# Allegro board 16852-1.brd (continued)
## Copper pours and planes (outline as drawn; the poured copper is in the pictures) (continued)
+DC_IN on L4: 51.56,119.87 49.28,119.87 49.02,119.62 49.02,111.36 53.82,106.56 60.76,106.56 61.98,107.78 61.98,110.09 61.21,110.86 56.77,110.86 52.58,115.05 52.58,118.86
+DC_IN on L6: 51.36,119.85 48.97,119.85 48.72,119.59 48.72,113.47 54.15,108.04 61.06,108.04 61.34,108.32 62.99,108.32 63.12,108.44 63.12,111.21 62.92,111.41 56.08,111.41 52.55,114.95 52.55,119.62 52.3,119.87 51.38,119.87
+DC_IN_C on TOP: 53.85,109.84 53.72,109.97 53.72,118.1 53.98,118.35 56.92,118.35 57.15,118.12 57.15,116.57 55.5,114.92 55.5,110.22 55.12,109.84 ; 3 cut-outs
+DC_IN_C on BOTTOM: 51.05,114.16 50.67,114.54 50.67,117.79 52.65,119.77 55.83,119.77 57.15,118.45 57.15,116.57 54.74,114.16
+SDC_IN on TOP: 66.42,104.13 66.29,104.25 66.29,106.92 66.93,107.55 69.34,107.55 69.47,107.43 69.47,106.28 69.6,106.16 70.56,106.16 70.84,105.88 70.84,105.62 71.17,105.29 71.81,105.29 71.86,105.24 72.67,105.24 72.77,105.14 72.77,104.25 72.64,104.13 ; 2 cut-outs
AD+ on TOP: 63.63,107.3 63.37,107.55 63.37,110.6 64.77,112 64.77,112.51 64.9,112.63 72.9,112.63 73.91,111.62 73.91,110.48 73.41,109.97 70.87,109.97 70.61,109.71 70.61,108.32 70.23,107.94 66.8,107.94 66.17,107.3 ; 5 cut-outs
AUD_AGND on TOP: 18.29,3.62 17.7,4.2 17.7,4.94 17.86,5.09 18.85,5.09 19.28,5.52 20.85,5.52 21.03,5.34 22,5.34 22.12,5.22 22.12,4.84 22.33,4.63 23.22,4.63 23.47,4.38 23.47,3.77 23.32,3.62 ; 5 cut-outs
AUD_AGND on TOP: 30.25,1.97 30.1,2.12 30.1,6.34 29.97,6.46 28.7,6.46 28.45,6.72 28.45,7.22 28.57,7.35 30.73,7.35 31.11,7.73 31.75,7.73 31.88,7.61 31.88,2.04 31.8,1.97 ; 5 cut-outs
AUD_AGND on L2VCC: 21.51,9.57 21.77,9.32 25.07,9.32 25.08,9.3 25.08,8.03 26.48,6.64 26.48,3.46 27.1,2.84 29.42,2.84 30.29,3.72 30.29,6.16 29.92,6.53 28.65,6.53 28.51,6.67 28.51,8.7 27.38,9.83 26.49,9.83 26.35,9.97 26.35,10.83 26.37,10.84 28.37,10.84 30.4,8.81 31.42,8.81 31.94,8.29 31.94,1.42 31.49,1.82 30.9,1.96 26.9,1.96 26.03,1.61 25.64,0.76 4.5,0.76 3.63,1.13 3.26,2 3.26,4.8 2.75,6.05 1.5,6.56 1,6.56 0.83,6.63 0.76,6.8 0.76,7.12 2.06,6.71 3.13,7.54 12.5,7.54 13.7,8.4 13.26,9.81 13.26,14.29 13.7,15.7 12.5,16.56 3.26,16.56 3.26,17.31 3.29,17.34 3.94,17.8 4.18,18.55 4.18,18.97 14.65,18.97 15.68,17.94 15.68,16.67 15.92,16.43 19.61,16.43 19.75,16.29 19.75,15.94 19.23,15.42 18.34,15.42 17.97,15.05 17.97,14.38 18.34,14.02 19.23,14.02 19.49,13.75 19.49,12.86 19.82,12.54 21.41,12.54 21.4,9.84 21.4,9.69
AUD_AGND on L5GND: 21.51,9.57 21.77,9.32 25.07,9.32 25.08,9.3 25.08,8.03 26.48,6.64 26.48,3.46 27.1,2.84 29.42,2.84 30.29,3.72 30.29,6.16 29.92,6.53 28.65,6.53 28.51,6.67 28.51,8.7 27.38,9.83 26.49,9.83 26.35,9.97 26.35,10.83 26.37,10.84 28.37,10.84 30.4,8.81 31.42,8.81 31.94,8.29 31.94,1.42 31.49,1.82 30.9,1.96 26.9,1.96 26.03,1.61 25.64,0.76 4.5,0.76 3.63,1.13 3.26,2 3.26,4.8 2.75,6.05 1.5,6.56 1,6.56 0.83,6.63 0.76,6.8 0.76,7.12 2.06,6.71 3.13,7.54 12.5,7.54 13.7,8.4 13.26,9.81 13.26,14.29 13.7,15.7 12.5,16.56 3.26,16.56 3.26,17.31 3.29,17.34 3.94,17.8 4.18,18.55 4.18,18.97 14.65,18.97 15.68,17.94 15.68,16.67 15.92,16.43 19.61,16.43 19.75,16.29 19.75,15.94 19.23,15.42 18.34,15.42 17.97,15.05 17.97,14.38 18.34,14.02 19.23,14.02 19.49,13.75 19.49,12.84 19.8,12.54 21.41,12.54 21.4,9.84 21.4,9.69
AUD_AGND on L7GND: 4.5,0.76 3.63,1.13 3.26,2 3.26,4.8 2.75,6.05 1.5,6.56 1,6.56 0.83,6.63 0.76,6.8 0.76,7.12 2.06,6.71 3.13,7.54 12.5,7.54 13.7,8.4 13.26,9.81 13.26,14.29 13.7,15.7 12.5,16.56 3.26,16.56 3.26,17.31 3.29,17.34 3.94,17.8 4.18,18.55 4.18,18.97 14.81,18.97 15.32,19.48 16.18,19.48 16.45,19.21 16.45,17.94 16.94,17.45 18.84,17.45 18.99,17.31 18.99,16.19 18.72,15.92 18.34,15.92 17.84,15.43 17.84,14.51 19.86,12.49 20.75,12.49 20.89,12.35 20.89,10.73 20.62,10.46 18.21,10.46 17.72,9.97 17.72,8.54 18.21,8.05 19.25,8.05 19.27,8.04 19.33,8.05 19.38,8.05 19.4,8.07 19.43,8.07 19.46,8.12 19.49,8.16 19.49,8.19 19.79,8.68 20.48,8.68 21.02,7.93 21.02,5.75 21.51,5.26 22.81,5.26 23.18,5.62 23.18,6.89 23.32,7.03 26.08,7.03 26.48,6.64 26.48,1.89 25.89,1.45 25.64,0.76
AUD_SPK_L+ on TOP: 33.73,9.87 33.6,9.99 33.6,10.22 33.35,10.48 29.84,10.48 28.8,11.52 26.49,11.52 26.47,11.54 26.47,11.69 26.49,11.72 29.34,11.72 29.49,11.57 34.39,11.57 34.47,11.49 34.47,9.99 34.34,9.87 ; 2 cut-outs
AUD_SPK_L+_C on TOP: 35,9.89 34.92,9.97 34.92,11.19 34.98,11.24 37.41,11.24 37.47,11.19 37.47,9.97 37.39,9.89
AUD_SPK_L+_C on BOTTOM: 34.24,9.51 33.68,10.07 31.11,10.07 31.06,10.12 31.06,11.64 31.14,11.72 34.24,11.72 34.67,11.29 36.37,11.29 36.63,11.03 36.63,9.69 36.45,9.51
AUD_SPK_L- on TOP: 29.62,11.67 29.36,11.92 26.47,11.92 26.44,11.95 26.44,12.1 26.47,12.13 29.01,12.13 29.21,12.33 30.28,12.33 30.68,12.74 34.39,12.74 34.49,12.63 34.49,11.77 34.39,11.67 ; 2 cut-outs
AUD_SPK_L-_C on TOP: 34.95,11.64 34.82,11.77 34.82,12.66 34.95,12.79 37.24,12.79 37.49,12.53 37.49,11.77 37.36,11.64
AUD_SPK_L-_C on BOTTOM: 34.11,7.45 33.43,8.14 30.89,8.14 30.07,8.95 30.07,11.67 30.18,11.77 30.89,11.77 30.89,10.04 31.09,9.84 33.6,9.84 34.54,8.9 36.09,8.9 36.88,9.69 36.88,11.24 36.68,11.44 36.04,11.44 35.97,11.52 35.97,12.41 36.14,12.58 38.15,12.58 38.79,11.95 38.79,8.09 38.15,7.45
AUD_SPK_R+ on TOP: 26.49,12.71 26.44,12.76 26.44,12.89 26.49,12.94 27.84,12.94 28.45,13.55 28.45,13.85 31.14,16.55 31.85,16.55 32.13,16.27 32.77,16.27 32.89,16.14 32.89,15.02 32.84,14.97 31.01,14.97 29.11,13.07 28.78,13.07 28.42,12.71 ; 2 cut-outs
AUD_SPK_R+_C on BOTTOM: 29.03,10.02 29.03,12.3 30.66,13.93 35.03,13.93 35.28,14.18 35.28,15.45 35.38,15.56 36.86,15.56 36.96,15.45 36.96,15.33 36.98,15.3 36.98,13.65 35.28,11.95 30.76,11.95 30.73,11.97 30.18,11.97 29.92,11.72 29.92,10.12 29.82,10.02
AUD_SPK_R- on TOP: 26.48,12.32 26.47,12.33 26.47,12.51 26.49,12.53 28.42,12.53 28.83,12.94 29.18,12.94 31.09,14.84 32.82,14.84 32.85,14.81 32.85,14.48 32.87,14.46 32.87,13.8 32.74,13.68 31.34,13.68 30.12,12.45 29.09,12.45 28.96,12.32 ; 2 cut-outs
AUD_SPK_R-_C on TOP: 33.48,13.4 33.35,13.52 33.35,14.54 33.78,14.97 34.82,14.97 35.71,14.08 35.71,13.57 35.53,13.4
AUD_SPK_R-_C on BOTTOM: 27.08,10.07 27,10.15 27,12.41 30.18,15.58 35.03,15.58 35.13,15.48 35.13,14.26 35,14.13 30.45,14.13 28.8,12.48 28.8,10.15 28.73,10.07
BT+ on TOP: 229.36,23.99 229.24,24.12 229.24,25.13 228.47,25.89 228.47,28.81 228.22,29.07 227.71,29.07 226.69,30.08 226.69,30.77 227.58,31.66 227.58,32.52 227.53,32.57 226.69,32.57 226.69,36.69 226.82,36.82 228.22,36.82 229.74,35.29 229.74,33.26 230.63,32.37 231.01,32.37 231.14,32.24 231.14,31.61 231.39,31.35 231.39,28.56 230.38,27.54 230.38,24.12 230.25,23.99 ; 3 cut-outs
BT+ on TOP: 236.09,22.06 235.97,22.18 235.97,23.1 236.09,23.23 236.85,23.23 236.98,23.1 236.98,22.29 236.75,22.06
BT+ on BOTTOM: 225.55,26.02 225.43,26.15 225.43,28.18 226.31,29.07 226.31,33.77 227.48,34.94 231.27,34.94 231.27,28.68 230.5,27.92 230.5,26.15 230.38,26.02
CHARGER_SRC on TOP: 220.18,18.12 220.01,18.29 220.01,24.37 219.99,24.39 219.99,26.81 220.12,26.93 223.27,26.93 223.52,26.68 223.52,24.32 222.81,23.6 222.81,23.6 222.81,19.93 223.06,19.69 224.37,19.69 224.54,19.52 224.54,18.15 224.51,18.12
CHARGER_SRC on BOTTOM: 220.6,20.81 220.09,21.32 220.09,25.13 220.34,25.39 222.25,25.39 222.63,25 222.63,23.61 222.25,23.23 222.25,21.45 221.62,20.81 ; 5 cut-outs
CHG_AGND on TOP: 241.02,12.08 240.92,12.18 240.92,12.56 241.05,12.69 241.94,12.69 242.06,12.81 242.06,15.48 242.19,15.61 243.28,15.61 243.43,15.45 243.43,14.26 242.95,13.78 242.95,12.3 242.72,12.08 ; 5 cut-outs
CHG_AGND on L6: 229.29,22.59 233.25,22.59 234.37,23.71 236.32,23.71 237.44,22.59 240.41,22.59 243.36,19.64 243.36,15.15 240.16,11.95 228.93,11.95 227.66,13.22 227.66,15.61 228.04,15.99 230.76,15.99 231.32,16.55 231.32,19.34 228.98,21.68 228.98,22.29
DCBATOUT on TOP: outline of 92 points within 51.18,63.38 84.39,103.62 ; 15 cut-outs
DCBATOUT on TOP: 221.22,15.76 220.13,16.85 220.13,17.71 220.28,17.87 225.4,17.87 225.76,17.51 226.67,17.51 226.72,17.46 226.72,16.24 226.24,15.76 ; 3 cut-outs
DCBATOUT on TOP: 218.19,34.66 218.19,36.05 217.81,36.43 217.81,37.83 218.19,38.21 218.19,41.39 216.92,42.66 216.92,43.93 217.55,44.56 217.55,45.2 216.34,46.4 216.34,47.55 215.52,48.37 215.52,52.82 216.53,53.83 220.47,53.83 220.48,53.85 220.9,53.43 220.9,47.69 224.28,44.31 224.28,40.27 222.68,38.67 222.68,37.93 222.5,37.75 222.48,37.75 222.3,37.58 221.39,37.58 220.93,37.12 220.93,34.73 220.85,34.66 ; 2 cut-outs
DCBATOUT on TOP: 106.17,123.56 105.92,123.81 105.92,127.75 106.17,128 146.69,128 147.04,127.65 147.04,125.61 146.51,125.08 145.36,125.08 145.24,125.21 138.2,125.21 137.82,124.83 113.67,124.83 113.41,125.08 111.38,125.08 109.86,123.56 ; 8 cut-outs
DCBATOUT on TOP: 46.61,35.8 46.48,35.93 46.48,39.99 46.23,40.24 43.18,40.24 42.93,40.5 42.93,42.66 43.05,42.78 43.69,42.78 44.07,43.17 44.07,47.23 44.2,47.36 46.35,47.36 46.61,47.1 46.61,44.82 46.3,44.51 46.3,42.02 46.35,41.97 47.04,41.97 47.75,41.26 47.88,41.26 49.28,39.86 49.28,37.83 50.42,36.69 50.42,35.93 50.29,35.8 ; 2 cut-outs
DCBATOUT on TOP: 201.45,71.11 201.43,71.12 200.11,71.12 199.59,71.64 199.59,86.45 200.79,87.64 202.72,87.64 203.58,88.5 203.58,88.89 203.33,89.14 203.33,91.93 206.25,94.85 206.25,96.63 203.58,99.3 203.58,101.64 199.87,105.34 199.87,114.56 202.06,116.75 202.06,118.02 202.46,118.43 202.46,120.66 203.02,121.22 203.91,121.22 204.06,121.37 204.06,124.14 204.62,124.7 210.9,124.7 211.02,124.57 211.02,121.3 211.35,120.97 211.35,117.03 211.2,116.88 209.91,116.88 209.52,117.26 207.98,117.26 207.92,117.21 207.9,117.21 207.75,117.05 207.75,110.35 207.01,109.61 207.01,106.16 207.9,105.27 207.9,101.46 208.41,100.95 210.57,100.95 212.72,98.79 213.01,98.52 213.23,97.6 213.23,96.51 212.98,96.25 210.29,96.25 208.69,94.65 208.69,91.55 206.98,89.85 206.98,88.02 206.43,87.46 205.97,87.46 204.09,85.58 204.09,82.41 203.07,81.39 203.07,78.98 204.09,77.96 204.09,74.05 204.94,73.2 205.42,73.2 205.54,73.09 205.54,72.04 204.6,71.11 ; 11 cut-outs
DCBATOUT on TOP: 215.9,68.82 215.52,69.2 215.52,71.31 215.62,71.41 215.82,71.41 215.9,71.49 215.9,74.4 216.03,74.53 216.28,74.53 216.28,74.53 217.19,74.53 218.06,69.02 218.1,68.82 ; 1 cut-out
DCBATOUT on TOP: 152.02,123.81 151.76,124.06 151.76,126.1 151.89,126.22 153.67,126.22 153.92,126.48 154.94,126.48 155.19,126.22 155.19,124.06 154.94,123.81 ; 3 cut-outs
DCBATOUT on BOTTOM: 218.72,35.88 218.54,36.05 218.54,47.58 216.38,49.74 216.38,53.78 216.51,53.91 219.56,53.91 220.22,53.25 220.22,51.98 219.46,51.22 219.46,50.02 220.55,48.93 220.55,47.61 221.41,46.75 221.41,37.75 221.23,37.58 220.7,37.58 220.6,37.48 220.6,36.79 219.68,35.88 ; 2 cut-outs
DCBATOUT on BOTTOM: 45.09,35.93 44.2,36.82 44.2,39.86 43.94,40.12 43.43,40.12 42.93,40.63 42.93,42.53 43.18,42.78 43.81,42.78 44.45,43.42 44.45,50.28 43.1,51.62 43.1,61.07 46.79,64.76 51.56,64.76 53.34,66.53 53.34,72.25 53.37,72.27 53.37,73.01 54.1,73.75 56.79,73.75 57.02,73.52 57.02,65.52 56.74,65.24 56.74,60.84 53.54,57.64 51.44,57.64 50.67,56.88 50.67,54.9 50.5,54.72 50.5,52.44 51.46,51.47 51.46,46.8 50.29,45.63 50.29,45.55 50.13,45.31 50.09,45.03 49.36,44.33 50.29,43.92 50.29,43.42 50.04,43.17 49.53,43.17 49.02,42.66 49.02,40.12 49.28,39.86 49.28,36.43 48.77,35.93 ; 2 cut-outs
DCBATOUT on BOTTOM: 115.95,123.05 113.69,125.31 110.95,125.31 109.98,124.34 109.98,123.68 109.86,123.56 106.17,123.56 105.92,123.81 105.92,127.87 106.17,128.13 156.84,128.13 157.61,127.37 157.61,123.3 157.35,123.05 154.94,123.05 154.18,123.81 151.89,123.81 151.76,123.94 151.76,125.21 151.51,125.46 130.94,125.46 130.68,125.21 127.64,125.21 127.38,125.46 121.03,125.46 118.62,123.05 ; 11 cut-outs
DCBATOUT on BOTTOM: 208.41,96 208.15,96.25 208.15,98.66 208.28,98.79 212.85,98.79 213.23,98.41 213.23,97.78 213.49,97.52 213.49,96.38 213.36,96.25 209.93,96.25 209.68,96 ; 2 cut-outs
DCBATOUT on BOTTOM: 216.15,69.07 215.52,69.71 215.52,71.33 215.54,71.36 215.85,71.36 215.93,71.44 215.93,74.97 216.13,75.17 217.09,75.17 217.91,69.96 217.91,69.56 217.42,69.07 ; 2 cut-outs
DCBATOUT on BOTTOM: 209.68,118.98 209.49,119.17 209.41,119.17 208.33,120.25 208.33,120.99 208.46,121.12 208.86,121.12 209.04,121.3 209.04,121.78 209.17,121.91 210.82,121.91 211.07,121.65 211.07,119.87 211.33,119.62 211.33,119.11 211.2,118.98 ; 2 cut-outs
DCBATOUT on L2VCC: 204.33,69.89 204.15,70.07 204.15,71.06 203.79,71.42 203.15,71.42 203.01,71.57 203.01,73.19 203.53,73.71 203.88,73.71 204.65,72.95 216.2,72.95 216.73,72.42 216.73,70.42 216.33,70.03 215.47,70.03 215.09,70.41 205.72,70.41 205.21,69.89
DCBATOUT on L3: 220.55,16.52 219.38,17.69 219.38,23.51 219.37,23.52 219.37,24.23 218.34,25.26 218.34,26.53 217.81,27.06 217.81,29.45 218.05,29.69 218.07,29.69 218.34,29.96 218.34,32.88 218.72,33.26 218.72,37.25 219.74,38.26 221.23,38.26 221.36,38.14 221.36,32.55 220.68,31.86 220.68,28.41 220.73,28.36 220.73,28.18 223.04,25.87 223.04,22.41 224.99,20.46 224.99,16.77 224.74,16.52 ; 1 cut-out
DCBATOUT on L3: 91.03,118.98 92.66,120.61 92.68,120.61 93.47,121.4 95.15,121.4 97.56,123.81 108.46,123.81 109.6,124.95 109.6,127.11 109.03,127.68 69.66,127.68 69.09,127.11 69.09,121.78 71.88,118.98
DCBATOUT on L3: 216.6,51.23 216.03,51.8 216.03,60.69 216.28,60.95 216.28,62.6 215.01,63.87 215.01,63.89 214.91,63.99 214.91,66.89 214.88,66.91 214.88,71.61 215.14,71.87 217.61,71.87 218.06,69.02 218.84,65.28 219.96,61.64 221.62,57.71 223.69,53.97 222.93,53.4 222,52.43 221.42,51.23
DCBATOUT on L4: 220.62,16.5 219.41,17.71 219.41,24.09 218.31,25.18 218.31,26.53 217.81,27.04 217.81,27.04 217.81,27.17 217.81,27.18 217.81,29.45 218.33,29.97 218.33,32.87 218.72,33.26 218.72,37.37 219.61,38.26 221.21,38.26 221.36,38.11 221.36,32.32 220.73,31.68 220.73,28.18 223.06,25.84 223.06,22.41 224.99,20.48 224.99,16.75 224.74,16.5 ; 1 cut-out
DCBATOUT on L4: 70.61,127.37 69.98,126.73 69.98,123.68 70.87,122.79 96.39,122.79 98.68,125.08 105.28,125.08 106.55,123.81 108.46,123.81 109.6,124.95 109.6,126.86 109.09,127.37
DCBATOUT on L4: 216.66,51.17 216.28,51.55 216.28,62.67 214.99,63.97 214.99,71.33 215.52,71.87 216.66,71.87 217.79,70.74 218.06,69.02 220.12,61.21 223.69,53.97 222.93,53.4 222.8,53.3 222.68,53.2 222.3,52.81 221.96,52.38 221.91,52.29 221.85,52.21 221.65,51.82 221.48,51.41 221.23,51.17
DCBATOUT on L6: 66.94,101.59 66.36,102.17 66.36,125.64 67.82,127.1 67.82,127.11 68.71,128 107.7,128 109.73,125.97 109.73,124.83 109.12,124.22 106.07,124.22 105.59,124.7 105.59,125.21 104.9,125.89 75.93,125.89 73.85,123.81 73.85,107.25 71.31,104.71 71.31,101.9 71,101.59
DCBATOUT on L6: 217.17,32.88 216.03,31.74 216.03,23.48 217.55,21.96 217.55,18.78 220.6,15.73 223.9,15.73 224.79,16.62 224.79,17.26 221.62,20.43 221.62,22.97 219.58,25 219.58,30.08 220.6,31.1 220.6,31.61 221.62,32.62 221.62,33.11 222.22,33.72 222.22,38.16 222.12,38.27 218.69,38.27 218.64,38.16 218.64,35.57 218.39,35.32 218.39,33.11 218.16,32.88
DCBATOUT on L6: outline of 88 points within 143.95,51.67 220.22,128.08 ; 2 cut-outs
DCBATOUT_+VCCSA on BOTTOM: 130.81,116.44 130.63,116.62 130.63,123.89 131.06,124.32 131.06,125.08 131.19,125.21 134.42,125.21 134.72,124.9 134.72,121.45 135.25,120.91 135.25,119.49 134.37,118.6 134.37,116.7 134.11,116.44 ; 3 cut-outs
DCBATOUT_CAMERA on BOTTOM: 70.1,88.5 69.85,88.76 69.85,91.04 69.98,91.17 70.99,91.17 70.99,88.63 70.87,88.5
DCBATOUT_LCD on TOP: 60.71,75.04 59.87,75.88 59.87,77.79 59.46,78.19 59.46,80.02 59.56,80.12 62.99,80.12 63.12,80 63.12,78.47 62.99,78.34 62.36,78.34 61.98,77.96 61.98,75.17 61.85,75.04 ; 5 cut-outs
DCBATOUT_LCD on BOTTOM: 59.05,74.86 58.98,74.94 58.98,76.69 59.21,76.92 60.91,76.92 61.21,76.62 61.21,75.02 61.06,74.86
DCBATOUT_VCCGT on TOP: 109.12,116.57 108.62,117.07 106.44,117.07 106.43,117.08 105.28,117.08 105.22,117.14 104.08,117.14 102.62,118.6 102.62,121.27 102.11,121.78 102.11,123.05 102.23,123.18 109.86,123.18 113.41,119.62 113.41,117.21 112.78,116.57
DCBATOUT_VCCGT on BOTTOM: 107.7,116.57 106.91,117.36 106.91,118.45 107.11,118.65 107.11,122.62 107.06,122.67 107.06,123.05 107.19,123.18 109.86,123.18 110.95,122.08 110.95,118.32 111.25,118.02 111.25,116.7 111.12,116.57 ; 2 cut-outs
DCBATOUT_VCORE on TOP: 116.71,120.25 116.59,120.38 116.59,121.78 116.71,121.91 117.35,121.91 117.6,122.16 117.6,124.19 117.98,124.57 125.48,124.57 125.98,124.06 125.98,121.27 124.97,120.25
DCBATOUT_VCORE on BOTTOM: 121.16,120.13 120.9,120.38 120.9,122.79 120.65,123.05 120.02,123.05 119.89,123.18 119.89,123.81 121.03,124.95 123.57,124.95 124.59,123.94 124.59,122.41 123.44,121.27 123.44,120.13 ; 3 cut-outs
DCBATOUT_VCORE on L3: 119.89,124.57 119.38,124.06 119.38,122.29 119.76,121.91 122.3,121.91 124.08,123.68 124.08,124.32 123.83,124.57
EMMC_RCOMP on TOP: 131.53,67.9 131.4,68.03 131.4,68.38 131.53,68.52 132.43,68.52 133.04,69.13 133.31,69.13 133.45,68.99 133.45,68.26 133.09,67.9
FAN_VCC1 on TOP: 212.42,46.14 212.34,46.21 212.34,47.43 211.23,48.55 211.23,50.1 211.66,50.53 213.13,50.53 213.21,50.45 213.21,49.01 213.41,48.8 213.41,46.29 213.26,46.14 ; 3 cut-outs
HDMI_PLL_GND on TOP: 22.73,63.49 22.73,66.03 22.86,66.15 22.86,70.72 26.29,74.15 28.57,74.15 28.7,74.03 28.7,73.52 26.8,71.61 25.78,71.61 24.51,70.34 24.51,68.31 24.26,68.06 24.26,63.74 24,63.49
ILIM_HI on TOP: 27.05,53.15 26.87,53.33 26.87,55.26 26.9,55.28 27.18,55.28 27.2,55.26 27.2,53.66 27.36,53.5 27.36,53.25 27.25,53.15
ILIM_HI on BOTTOM: 25.91,53.15 25.76,53.3 25.76,54.04 26.19,54.47 27.15,54.47 27.3,54.32 27.3,53.2 27.25,53.15 ; 1 cut-out
JGND on TOP: 49.15,104.13 49.02,104.25 49.02,109.71 49.66,110.35 50.8,110.35 52.07,111.62 52.07,114.16 52.32,114.41 53.34,114.41 53.59,114.16 53.59,107.55 55.5,105.65 55.5,104.76 55.24,104.51 51.18,104.51 50.8,104.13 ; 4 cut-outs
JGND on BOTTOM: 50.55,105.52 50.04,106.03 50.04,109.46 51.05,110.48 54.1,110.48 54.48,110.09 54.48,106.28 53.72,105.52
LAN_REGOUT on TOP: 47.88,88.12 47.37,88.63 47.12,88.63 46.99,88.76 46.99,89.27 47.12,89.39 47.75,89.39 48.01,89.65 51.56,89.65 51.69,89.52 51.69,88.25 51.56,88.12
LAN_REGOUT on BOTTOM: 45.97,92.7 45.85,92.82 45.85,93.71 46.74,93.71 46.74,93.46 46.99,93.2 46.99,92.82 46.86,92.7
LAN_REGOUT on L3: 46.23,93.58 48.77,93.58 49.66,92.7 49.66,89.14 49.28,88.76 47.5,88.76 45.59,90.66 45.59,92.95
LCDVDD on BOTTOM: 60.1,83.53 59.97,83.65 59.97,86.22 60.15,86.4 62.53,86.4 62.69,86.24 62.69,85.51 62.23,85.05 62.23,83.65 62.1,83.53
LCDVDD_LCD on BOTTOM: 56.64,74.92 56.52,75.04 56.52,76.31 55.55,77.28 55.55,80.91 55.82,81.18 56.71,81.18 57.07,81.54 59.02,81.54 60.02,82.55 60.03,82.55 60.06,82.58 60.06,82.95 60.33,83.22 62.76,83.22 62.92,83.07 62.92,81.37 62.48,80.93 62.48,80.43 61.24,79.18 61.24,77.43 60.88,77.07 58.98,77.07 58.29,76.39 58.29,74.92 ; 2 cut-outs
LOM_TCT on TOP: 24.51,85.58 24.26,85.84 24.26,97.52 25.15,98.41 26.04,98.41 26.16,98.28 26.16,97.27 25.53,96.63 25.53,85.84 25.27,85.58
MCT on TOP: 18.47,84.52 18.36,84.62 18.36,85.81 18.69,86.14 19.53,86.14 20.83,87.44 20.83,91.43 20.95,91.55 22.48,91.55 22.73,91.3 22.73,84.69 22.56,84.52
PWR_0D95V on BOTTOM: 169.29,57.26 169.16,57.39 169.16,64.3 169.37,64.5 171.63,64.5 171.83,64.3 171.83,61.33 170.81,60.31 170.81,57.39 170.69,57.26 ; 3 cut-outs
PWR_0D95V_PHASE on BOTTOM: 171.81,57.14 171.6,57.34 171.6,60.41 171.83,60.64 173.2,60.64 174.68,59.17 175.26,59.17 175.39,59.04 175.39,58.79 175.26,58.66 174.88,58.66 174.65,58.43 174.65,57.64 174.14,57.14
PWR_0D95V_PVDD on BOTTOM: 178.44,55.74 178.38,55.79 176.71,55.79 176.53,55.97 176.53,57.47 176.71,57.64 177.5,57.64 177.9,58.05 177.9,58.56 177.72,58.74 176.91,58.74 176.86,58.79 176.86,59.07 176.91,59.12 178.31,59.12 178.36,59.17 179.2,59.17 179.45,58.91 179.45,55.87 179.32,55.74 ; 3 cut-outs
PWR_1D0V_PH on TOP: 36.58,25.77 36.47,25.87 36.47,28.97 36.63,29.12 38.56,29.12 39.75,27.93 42.16,27.93 42.29,28.05 42.29,30.85 42.42,30.97 43.43,30.97 43.56,30.85 43.56,27.29 43.31,27.04 42.8,27.04 42.67,26.91 42.67,26.27 42.16,25.77
PWR_1D0V_PH on BOTTOM: 32.64,25.77 32.38,26.02 32.38,29.45 32.51,29.58 38.1,29.58 40.01,27.67 40.01,26.25 39.52,25.77
PWR_1D5V on TOP: 191.64,120.25 191.39,120.51 191.39,125.46 191.52,125.59 197.79,125.59 197.99,125.38 197.99,120.48 197.76,120.25
PWR_1D5V on BOTTOM: 192.15,120.1 191.97,120.28 191.97,126.15 191.9,126.22 191.9,126.5 192.48,127.09 196.32,127.09 197.05,127.82 198.75,127.82 198.91,127.67 198.91,126.2 197.36,124.65 197.36,121.78 196.85,121.27 196.6,121.27 196.47,121.14 196.47,120.25 193.5,120.25 193.34,120.1
PWR_1D35V_PH on BOTTOM: 198.4,120.25 198.15,120.51 198.15,124.45 198.4,124.7 202.82,124.7 202.95,124.57 202.95,123.68 203.07,123.56 203.33,123.56 203.71,123.18 203.71,121.78 203.96,121.52 203.96,121.4 201.93,121.4 201.8,121.27 201.8,120.38 201.68,120.25 ; 1 cut-out
PWR_2D5V on BOTTOM: 64.26,4.68 64.14,4.81 59.82,4.81 59.56,5.07 59.56,5.6 59.26,5.9 59.26,7.91 60.6,9.26 62.87,9.26 63.12,9 63.12,6.92 63.25,6.79 64.59,6.79 64.74,6.64 64.74,4.76 64.67,4.68 ; 5 cut-outs
PWR_2D5V_FB on BOTTOM: 62.08,3.13 61.67,3.54 59.69,3.54 59.56,3.67 59.56,4.43 59.69,4.56 63.88,4.56 64.39,4.05 64.39,3.29 64.24,3.13 ; 3 cut-outs
PWR_3D3V on TOP: 24.89,41.13 24.51,41.51 24.51,45.58 24.64,45.71 30.86,45.71 31.5,45.07 31.5,41.51 31.11,41.13 ; 2 cut-outs
PWR_3D3V on BOTTOM: 25.65,41.13 25.53,41.26 25.53,47.79 25.68,47.94 28.96,47.94 29.21,47.69 29.21,46.31 29.31,46.21 31.83,46.21 32.51,45.53 32.51,41.64 32,41.13
PWR_3D3V_HG on TOP: 51.23,43.93 51.18,43.98 51.18,44.33 50.52,44.99 50.52,45.48 50.65,45.6 51.13,45.6 51.46,45.27 51.46,43.95 51.44,43.93
PWR_3D3V_LG on TOP: 50.16,43.52 49.5,44.18 49.5,44.69 49.66,44.84 50.06,44.84 50.6,44.31 50.6,44.05 50.83,43.83 50.98,43.83 51.05,43.75 51.05,43.52
PWR_3D3V_PH on TOP: 52.12,45.25 50.57,46.8 50.57,47.53 50.65,47.61 51.66,47.61 51.74,47.53 51.74,46.82 52.55,46.01 52.55,45.37 52.43,45.25
PWR_3D3V_PH on TOP: 34.47,40.75 34.39,40.83 34.39,46.04 35.66,47.31 38.4,47.31 38.48,47.23 38.48,43.93 38.46,43.95 37.19,43.95 37.08,43.85 37.08,40.88 36.96,40.75
PWR_3D3V_PH on BOTTOM: 34.52,40.7 34.39,40.83 34.39,46.04 34.95,46.59 37.59,46.59 38.35,45.83 38.35,41.26 37.8,40.7
PWR_5V on TOP: 23.24,29.7 23.11,29.83 23.11,31.61 23.37,31.86 23.37,34.66 24.26,35.55 30.61,35.55 31.75,34.4 31.75,30.85 30.71,29.8 29.69,29.8 29.59,29.7 ; 2 cut-outs
PWR_5V on BOTTOM: 22.99,29.07 22.48,29.58 22.48,33.01 22.99,33.51 25.4,33.51 28.32,36.43 31.75,36.43 32.51,35.67 32.51,32.12 30.57,30.17 27.39,30.17 27.23,30.01 27.23,29.17 27.13,29.07
PWR_5V_HG on TOP: 50.39,40.09 50.22,40.27 50.22,40.78 51.21,41.77 51.44,41.77 51.44,40.78 50.75,40.09
PWR_5V_LG on TOP: 49.35,41.16 49.33,41.18 49.33,42 49.4,42.07 50.01,42.07 50.09,42.15 51.05,42.15 51.08,42.12 51.08,41.9 51.05,41.87 50.65,41.87 49.94,41.16
PWR_5V_PH on TOP: 34.87,30.64 33.91,31.61 33.91,37.58 34.28,37.95 36.69,37.95 36.8,37.83 36.8,36.26 36.73,36.18 35.74,36.18 35.69,36.13 35.69,35.29 36.65,34.33 38.25,34.33 38.61,33.97 38.61,30.64
PWR_5V_PH on TOP: 51.51,38.57 51.33,38.75 51.33,39.66 51.97,40.29 51.97,40.65 52.02,40.7 52.53,40.7 52.68,40.55 52.68,39.81 52.6,39.74 52.6,38.75 52.43,38.57
PWR_5V_PH on BOTTOM: 34.77,30.74 33.91,31.61 33.91,37.58 34.29,37.96 38.23,37.96 38.48,37.7 38.48,31.38 37.85,30.74
PWR_5V_VO on TOP: 58.42,38.21 58.29,38.34 58.29,40.24 57.66,40.88 57.66,41.13 57.78,41.26 58.17,41.26 58.93,40.5 58.93,38.34 58.8,38.21
PWR_CHG_PHASE on TOP: 224.54,25.87 223.67,26.73 223.67,27.34 223.44,27.57 221.41,27.57 221.31,27.67 221.31,30.54 222.25,31.48 224.54,31.48 227.46,28.56 227.84,28.56 227.97,28.43 227.97,25.99 227.84,25.87
PWR_CHG_PHASE on BOTTOM: 222.68,26.73 220.75,28.66 220.75,31.66 220.78,31.68 224.35,31.68 225.14,30.9 225.14,28.91 224.56,28.33 224.56,27.06 224.23,26.73
PWR_CHG_PHASE_1 on TOP: 221.23,32.24 221.16,32.32 221.16,36.84 225.76,36.84 226.09,36.51 226.09,32.62 225.7,32.24
PWR_CHG_PHASE_1 on BOTTOM: 221.23,32.37 220.85,32.75 220.85,37.2 220.98,37.32 224.51,37.32 225.02,36.82 225.02,32.45 224.94,32.37
PWR_DCBATOUT_1D0V on TOP: 44.07,27.04 43.81,27.29 43.81,31.23 43.94,31.35 43.94,32.24 44.07,32.37 45.09,32.37 46.1,33.39 46.1,35.04 46.41,35.34 49.5,35.34 49.59,35.25 49.59,34.82 49.23,34.45 49.23,31.14 48.89,30.81 47.99,30.81 47.73,31.07 47.09,31.07 46.74,30.72 46.74,30.71 46.51,30.48 45.74,30.48 45.09,29.83 45.09,27.16 44.96,27.04 ; 3 cut-outs
PWR_DCBATOUT_1D35V on BOTTOM: 204.34,122.16 204.22,122.29 204.22,123.53 205.38,124.7 206.35,124.7 206.36,124.69 210.73,124.69 210.96,124.46 210.96,122.41 210.95,122.41 210.72,122.18 205.64,122.18 205.61,122.16 ; 4 cut-outs
PWR_DCBATOUT_3D3V on TOP: 37.47,39.51 37.47,42.78 37.85,43.17 41.78,43.17 42.16,42.78 42.42,42.78 42.55,42.66 42.55,40.63 42.24,40.32 40.97,40.32 40.16,39.51 ; 2 cut-outs
PWR_DCBATOUT_5V on TOP: 37.41,35.04 37.34,35.11 37.34,38.36 37.39,38.42 40.21,38.42 41.66,39.86 46.23,39.86 46.23,35.67 45.97,35.42 40.64,35.42 40.26,35.04 ; 2 cut-outs
PWR_DCBATOUT_VDDQ on TOP: 61.59,68.57 61.09,69.07 59.05,69.07 58.8,69.33 58.8,69.89 58.55,70.14 58.55,71.84 58.7,71.99 63.88,71.99 64.01,71.87 64.01,71.23 62.81,70.04 62.81,68.64 62.74,68.57 ; 1 cut-out
PWR_DCBATOUT_VGA_CORE1 on TOP: 208.46,71.23 208.2,71.49 208.2,72.32 208.65,72.77 209.69,72.77 209.93,73.01 209.93,74.15 209.68,74.41 208.66,74.41 208.53,74.53 208.53,75.04 208.79,75.3 214.15,75.3 214.22,75.37 215.37,75.37 215.67,75.07 215.67,71.61 215.62,71.56 215.09,71.56 214.76,71.23 ; 2 cut-outs
PWR_DCBATOUT_VGA_CORE1 on BOTTOM: 209.19,71.23 208.86,71.56 208.86,74.13 208.53,74.46 208.53,75.04 208.79,75.3 214.45,75.3 215.16,75.29 215.26,75.3 215.65,74.91 215.65,71.66 215.6,71.61 215.26,71.61 214.91,71.28 214.76,71.23 ; 2 cut-outs
PWR_DCBATOUT_VGA_CORE2 on TOP: 207.65,87.49 207.14,88 207.14,89.67 208.43,90.97 211,90.97 211.33,91.3 211.33,94.85 211.07,95.11 210.44,95.11 210.31,95.24 210.31,95.87 210.44,96 213.49,96 213.83,95.65 215.13,87.49 ; 2 cut-outs
PWR_DCBATOUT_VGA_CORE2 on BOTTOM: 207.14,87.49 206.76,87.87 206.76,89.77 207.71,90.73 211.14,90.73 211.46,91.04 211.46,94.85 211.33,94.98 210.69,94.98 210.31,95.36 210.31,95.87 210.44,96 213.78,96 215.06,87.92 214.63,87.49 ; 2 cut-outs
PWR_VCCGT_GL1 on BOTTOM: 111.89,112.13 111.76,112.25 111.76,113.4 111.89,113.52 113.16,113.52 113.28,113.4 113.28,112.25 113.16,112.13
PWR_VCCGT_SWA on BOTTOM: 107.31,108.65 107.11,108.85 107.11,109.28 106.93,109.46 106.93,110.35 107.06,110.48 108.71,110.48 108.84,110.6 108.84,113.4 108.97,113.52 111.51,113.52 111.63,113.4 111.63,111.87 111.89,111.62 114.55,111.62 114.68,111.49 114.68,108.8 114.53,108.65
PWR_VCCSA_DRVL on BOTTOM: 139.52,118.02 139.45,118.1 139.45,122.06 139.6,122.21 140,122.21 140.11,122.11 140.11,120.76 140.31,120.56 140.31,118.22 140.11,118.02
PWR_VCCSA_SW on BOTTOM: 137.79,121.02 137.29,121.52 137.29,122.92 137.67,123.3 139.06,123.3 139.19,123.18 139.19,122.92 138.43,122.16 138.43,121.27 138.18,121.02 ; 1 cut-out
PWR_VCCSA_SW on BOTTOM: 133.73,110.98 131.83,112.89 131.83,116.19 136.53,116.19 136.78,116.44 136.78,117.71 136.91,117.84 140.23,117.84 140.41,117.66 140.41,114.74 138.56,112.89 138.56,111.49 138.05,110.98
PWR_VCORE_BOOT_RC on BOTTOM: 124.84,123.94 124.08,124.7 124.08,125.08 124.31,125.31 127.28,125.31 127.51,125.08 127.51,124.19 127.25,123.94 ; 2 cut-outs
PWR_VCORE_GL on BOTTOM: 124.21,115.94 124.08,116.06 124.08,116.95 124.21,117.08 125.35,117.08 125.48,116.95 125.48,116.06 125.35,115.94
PWR_VCORE_SW on BOTTOM: 118.94,112.06 118.24,112.76 118.24,114.03 118.36,114.16 120.14,114.16 120.4,114.41 120.4,116.83 120.65,117.08 123.83,117.08 123.95,116.95 123.95,115.81 124.08,115.68 125.6,115.68 125.98,115.3 125.98,112.38 125.86,112.25 120.78,112.25 120.59,112.06
PWR_VDDQ on TOP: 63.3,53.07 63.2,53.17 63.2,54.54 64.14,55.48 66.55,55.48 66.67,55.61 66.67,56.37 66.8,56.5 67.94,56.5 68.2,56.75 68.2,59.24 68.25,59.29 71.63,59.29 71.87,59.05 71.87,56 71.88,55.99 71.88,54.34 71.75,54.21 66.8,54.21 66.17,53.58 66.17,53.33 65.91,53.07 ; 4 cut-outs
PWR_VDDQ on BOTTOM: 68.2,55.61 68.07,55.74 68.07,62.85 68.2,62.98 71.75,62.98 71.88,62.85 71.88,55.99 71.5,55.61
PWR_VDDQ_PH on TOP: 66.19,66.28 65.52,66.95 65.52,67.69 65.15,68.06 63.12,68.06 63.07,68.11 63.07,68.39 63.41,68.73 63.41,69.24 63.63,69.45 63.63,69.84 64.01,70.22 66.55,70.22 66.56,70.23 68.72,70.23 69.06,69.89 69.06,66.53 68.81,66.28 ; 2 cut-outs
PWR_VDDQ_PH on BOTTOM: 67.01,64.12 66.1,65.02 66.1,66.22 65.66,66.66 65.66,67.98 65.25,68.39 64.67,68.39 64.57,68.49 64.57,69.25 64.8,69.48 64.8,69.99 65.02,70.22 70.87,70.22 71.5,69.58 71.5,69.56 72.75,68.31 72.75,64.55 72.31,64.12
PWR_VGA_CORE_PHASE1 on TOP: 204.98,73.26 204.47,73.77 204.47,78.73 204.6,78.85 214.43,78.85 214.76,78.52 214.76,76.31 214.12,75.68 208.03,75.68 207.65,75.3 207.65,73.39 207.52,73.26 ; 1 cut-out
PWR_VGA_CORE_PHASE1 on BOTTOM: 204.98,73.26 204.85,73.39 204.85,77.84 205.74,78.73 213.49,78.73 213.61,78.85 213.61,79.11 213.74,79.23 214.53,79.23 214.73,79.03 214.73,76.03 214.5,75.8 208.15,75.8 207.65,75.3 207.65,73.39 207.52,73.26
PWR_VGA_CORE_PHASE1 on L4: 206.58,77.68 206.07,77.68 205.97,77.58 205.97,75.93 206.17,75.73 207.37,75.73 207.42,75.78 207.42,75.96 206.68,76.69 206.68,77.58
PWR_VGA_CORE_PHASE1 on L6: 214.63,78.98 204.72,78.98 204.47,78.73 204.47,73.77 204.98,73.26 207.52,73.26 207.65,73.39 207.65,75.3 207.9,75.55 214.76,75.55 215.01,75.8 215.01,78.6
PWR_VGA_CORE_PHASE2 on TOP: 204.6,81.52 204.47,81.65 204.47,85.58 205.87,86.98 213.61,86.98 214,86.6 214,84.19 213.74,83.93 208.03,83.93 207.65,83.55 207.65,82.66 206.5,81.52 ; 1 cut-out
PWR_VGA_CORE_PHASE2 on BOTTOM: 204.98,81.01 204.85,81.14 204.85,86.22 205.84,87.21 207.49,87.21 207.59,87.11 208.38,87.11 208.51,86.98 213.74,86.98 214,86.73 214,84.19 213.74,83.93 208.03,83.93 207.65,83.55 207.65,81.14 207.52,81.01
PWR_VGA_CORE_PHASE2 on L4: 204.7,85.2 203.91,84.41 203.91,84.26 204.5,83.68 204.65,83.68 205.59,84.62 205.59,85.02 205.41,85.2
PWR_VGA_CORE_PHASE2 on L6: 205.87,86.98 213.61,86.98 214,86.6 214,84.19 213.74,83.93 208.03,83.93 207.65,83.55 207.65,82.66 206.5,81.52 204.6,81.52 204.47,81.65 204.47,85.58
PWR_VGA_CORE_UGATE_LX_NB on TOP: 200.03,64.37 199.9,64.5 199.9,65.01 200.03,65.14 201.8,65.14 201.93,65.01 201.93,64.5 201.8,64.37
RING2 on TOP: 19.43,12.3 19.3,12.43 18.54,12.43 17.53,13.45 17.53,14.11 17.63,14.21 19.05,14.21 19.81,13.45 19.81,12.43 19.68,12.3
SLEEVE on TOP: 17.53,10.53 17.4,10.65 17.4,11.42 18.16,12.18 20.07,12.18 20.32,11.92 19.43,11.92 18.03,10.53 ; 1 cut-out
TP_VDD on TOP: 135,5.32 134.75,5.57 134.75,8.11 135.13,8.49 137.03,8.49 137.16,8.37 137.16,8.11 136.65,7.61 136.65,5.7 136.27,5.32
TP_VDD on BOTTOM: 135.13,3.54 135,3.67 135,5.07 134.75,5.32 134.75,5.83 134.87,5.95 137.67,5.95 137.79,5.83 137.79,4.68 136.65,3.54
TPAN_VDD_F on TOP: 38.99,73.52 38.61,73.9 38.61,75.68 38.35,75.93 38.35,76.95 38.23,77.07 37.97,77.07 37.85,77.2 37.85,77.96 37.97,78.09 40.13,78.09 40.51,77.71 40.51,73.9 40.13,73.52 ; 2 cut-outs
U4101_OUT on TOP: 150.62,47.61 149.61,48.63 148.21,48.63 148.08,48.75 148.08,49.39 148.21,49.52 150.37,49.52 150.5,49.39 152.02,49.39 152.15,49.26 152.15,47.74 152.02,47.61
USB20_VCCA on BOTTOM: 277.83,25.84 277.65,26.02 277.65,27.11 278.03,27.49 278.03,33.79 278.13,33.89 278.94,33.89 280.04,32.8 281.89,32.8 282.3,32.4 282.3,29.2 281.89,28.79 280.31,28.79 279.83,28.31 279.83,26.05 279.63,25.84 ; 5 cut-outs
USB30_VCCB on TOP: 17.27,29.32 13.72,32.88 13.72,34.4 13.97,34.66 15.88,34.66 17.27,33.26 20.45,33.26 21.34,32.37 21.34,29.58 21.08,29.32 ; 4 cut-outs
USB30_VCCB on BOTTOM: 17.91,28.81 17.78,28.94 17.78,30.08 18.67,30.97 18.67,32.62 18.8,32.75 20.57,32.75 21.21,32.12 21.21,30.08 19.94,28.81
USB30_VCCC on TOP: 21.84,52.69 21.72,52.82 21.72,55.61 21.89,55.79 25.15,55.79 25.2,55.74 25.2,52.87 25.02,52.69 ; 1 cut-out
USB30_VCCC on TOP: 13.74,52.54 13.34,52.94 13.34,54.47 15.11,56.25 15.11,57.01 14.1,58.02 14.1,60.44 14.48,60.82 17.53,60.82 18.8,59.55 18.8,52.79 18.54,52.54
USB30_VCCC on BOTTOM: 22.35,54.34 22.1,54.6 22.1,55.36 22.23,55.48 23.5,55.48 23.88,55.87 23.88,57.14 22.23,58.79 15.37,58.79 14.99,59.17 14.99,60.56 15.37,60.95 20.83,60.95 21.08,60.69 23.11,60.69 25.27,58.53 25.27,54.6 25.02,54.34 ; 6 cut-outs
USB30_VCCC on L3: 24.69,54.21 25.37,54.9 25.37,57.06 19.96,62.47 14.99,62.47 14.71,62.19 14.71,59.55 15.95,58.3 20.35,58.3 21.83,56.82 21.83,54.94 22.56,54.21
VGA_CORE on TOP: outline of 86 points within 172.24,74.75 181.18,84.85 ; 13 cut-outs
VGA_CORE on TOP: 185.29,64.76 184.53,65.52 184.53,68.44 184.91,68.82 189.23,68.82 190.37,69.96 190.37,75.55 196.22,81.39 198.63,81.39 198.88,81.14 198.88,65.01 198.63,64.76 ; 8 cut-outs
VGA_CORE on TOP: 181.79,79.31 181.71,79.39 181.71,79.64 181.58,79.77 181.05,79.77 180.98,79.84 180.98,81.08 181.57,81.67 182.83,81.67 183,81.5 183,79.81 182.51,79.31 ; 3 cut-outs
VGA_CORE on BOTTOM: 193.17,71.61 192.66,72.12 192.66,77.84 199.26,84.44 201.68,84.44 201.93,84.19 201.93,72.76 200.79,71.61
VGA_CORE on BOTTOM: 195.58,63.49 194.31,64.76 185.29,64.76 184.53,65.52 184.53,67.42 184.91,67.8 186.18,67.8 187.2,68.82 192.28,68.82 193.42,67.68 198.5,67.68 198.88,67.3 198.88,63.99 198.37,63.49 ; 10 cut-outs
VGA_CORE on BOTTOM: outline of 81 points within 172.72,74.79 182.88,84.95 ; 1 cut-out
VGA_CORE on L2VCC: 178.01,65.71 170.24,73.47 170.24,84.11 170.89,84.76 194.23,84.76 195.77,83.22 195.77,65.98 195.5,65.71
VGA_CORE on L6: 179.53,64.06 169.86,73.72 169.86,77.41 167.32,79.95 167.32,83.22 169.18,85.08 191.13,85.08 191.16,85.1 194.09,85.1 194.37,84.82 194.44,84.82 195.71,83.55 195.71,64.86 194.87,64.06

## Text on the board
Ref Des/Silkscreen Bottom: M2 | SPK | LCD | DC-IN | IR | X3101:25MHZ | X1801:24MHZ | X7901:27MHZ | X1802:32.768KHZ | FAN | DB2 | RTC | Battery | HDD | DB | DB VGA | WLAN | WWAN | DDR4(A) | DDR4(B)
Ref Des/Silkscreen Top: Taos | 16852-1 | D5FVH | MADE IN TAIWAN | H-Sensor | TP | KB backlit | LED | POWER | FPR | F5503:1.1A/24V | F5502:1.1A/6V | X2401:32.768KHZ | KB
User.30: AUD_AGND | 3D3V_S5 | +VCCGT | VCC_CORE | +VCCSA | +V1.00A_SIP | +VCCMPHYGTAON_1P0_LS_SIP | +VCCSRAM_1P0 | 5V_S5 | +VCCPRIM_CORE | 5V_S0 | +VCCIO | 1D0V_S5 | VGA_CORE | DCBATOUT | GND | 3D3V_S0
User.31: AUD_AGND | GND
User.33: ByImpedance:100.0@_REF_L1=("4.0/6.0(L2)" "3.5/5.0(L2)" "5.0/11.0(L2)")|_REF_L6=("4.0/10.0(L5/L7)" "3.5/7.0(L5/L7)")|Type="DP"|_REF_L4=("3.5/7.5(L3/L5)" "4.0/9.0(L2/L5)" "3.5/7.0(L2/L5)")|_REF_L3=("4.0/9.0(L2/L5)" "3.5/7.0(L2/L5)")|imp="100.0"|_REF_L8=("4.0/6.0(L7)" "3.5/5.0(L7)" "5.0/11.0(L7)") | ByImpedance:110.0@_REF_L1=("4.0/12.0(L2)" "3.5/8.0(L2)")|Type="DP"|imp="110.0"|_REF_L8=("4.0/12.0(L7)" "3.5/8.0(L7)") | ByImpedance:27.4@_REF_L1=("16.0(L2)")|_REF_L6=("13.5(L5/L7)")|Type="SE"|_REF_L4=("13.5(L3/L5)" "15.0(L2/L5)")|_REF_L3=("15.0(L2/L5)")|imp="27.4"|_REF_L8=("16.0(L7)") | ByImpedance:33.0@_REF_L1=("12.0(L2)")|_REF_L6=("10.0(L5/L7)")|Type="SE"|_REF_L4=("10.0(L3/L5)" "11.0(L2/L5)")|_REF_L3=("11.0(L2/L5)")|imp="33.0"|_REF_L8=("12.0(L7)") | ByImpedance:35.0@_REF_L1=("11.0(L2)")|_REF_L6=("9.0(L5/L7)")|Type="SE"|_REF_L4=("10.0(L2/L5)" "9.0(L3/L5)")|_REF_L3=("10.0(L2/L5)")|imp="35.0"|_REF_L8=("11.0(L7)") | ByImpedance:37.5@_REF_L1=("10.0(L2)")|_REF_L6=("8.0(L5/L7)")|Type="SE"|_REF_L4=("8.0(L3/L5)" "9.0(L2/L5)")|_REF_L3=("9.0(L2/L5)")|imp="37.5"|_REF_L8=("10.0(L7)") | ByImpedance:39.0@_REF_L1=("9.0(L2)")|_REF_L6=("7.5(L5/L7)")|Type="SE"|_REF_L4=("8.5(L2/L5)" "7.5(L3/L5)")|_REF_L3=("8.5(L2/L5)")|imp="39.0"|_REF_L8=("9.0(L7)") | ByImpedance:40.0@_REF_L1=("8.5(L2)")|_REF_L6=("7.0(L5/L7)")|Type="SE"|_REF_L4=("7.0(L3/L5)" "8.0(L2/L5)")|_REF_L3=("8.0(L2/L5)" "7.0(L2/L4)")|imp="40.0"|_REF_L8=("8.5(L7)") | ByImpedance:45.0@_REF_L1=("7.0(L2)")|_REF_L6=("5.5(L5/L7)")|Type="SE"|_REF_L4=("6.0(L2/L5)" "5.5(L3/L5)")|_REF_L3=("6.0(L2/L5)" "5.5(L2/L4)")|imp="45.0"|_REF_L8=("7.0(L7)") | ByImpedance:48.0@_REF_L1=("6.0(L2)")|_REF_L6=("5.0(L5/L7)")|Type="SE"|_REF_L4=("5.0(L3/L5)" "5.5(L2/L5)")|_REF_L3=("5.5(L2/L5)" "5.0(L2/L4)")|imp="48.0"|_REF_L8=("6.0(L7)") | ByImpedance:50.0@_REF_L1=("5.5(L2)")|_REF_L6=("4.5(L5/L7)")|Type="SE"|_REF_L4=("4.5(L3/L5)" "5.0(L2/L5)")|_REF_L3=("4.5(L2/L4)" "5.0(L2/L5)")|imp="50.0"|_REF_L8=("5.5(L7)") | ByImpedance:52.0@_REF_L1=("5.0(L2)")|_REF_L6=("4.0(L5/L7)")|Type="SE"|_REF_L4=("4.5(L2/L5)" "4.0(L3/L5)")|_REF_L3=("4.5(L2/L5)" "4.0(L2/L4)")|imp="52.0"|_REF_L8=("5.0(L7)") | ByImpedance:55.0@_REF_L1=("4.5(L2)")|_REF_L6=("3.5(L5/L7)")|Type="SE"|_REF_L4=("4.0(L2/L5)" "3.5(L3/L5)")|_REF_L3=("4.0(L2/L5)")|imp="55.0"|_REF_L8=("4.5(L7)") | ByImpedance:60.0@_REF_L1=("11.5/5.0(L2)")|_REF_L6=("10.5/5.0(L5/L7)")|Type="DP"|_REF_L4=("9.0/4.0(L3/L5)" "9.5/4.0(L2/L5)")|_REF_L3=("9.5/4.0(L2/L5)")|imp="60.0"|_REF_L8=("11.5/5.0(L7)") | ByImpedance:68.0@_REF_L1=("9.0/5.0(L2)")|_REF_L6=("7.5/5.0(L5/L7)")|Type="DP"|_REF_L4=("7.0/4.0(L3/L5)" "7.5/4.0(L2/L5)")|_REF_L3=("7.5/4.0(L2/L5)")|imp="68.0"|_REF_L8=("9.0/5.0(L7)") | ByImpedance:70.0@_REF_L1=("8.5/5.0(L2)")|_REF_L6=("7.0/5.0(L5/L7)")|Type="DP"|_REF_L4=("7.0/4.0(L2/L5)" "6.5/4.0(L3/L5)")|_REF_L3=("7.0/4.0(L2/L5)")|imp="70.0"|_REF_L8=("8.5/5.0(L7)") | ByImpedance:72.0@_REF_L1=("8.0/5.0(L2)")|_REF_L6=("6.0/4.0(L5/L7)")|Type="DP"|_REF_L4=("7.0/5.0(L2/L5)" "6.0/4.0(L3/L5)")|_REF_L3=("7.0/5.0(L2/L5)")|imp="72.0"|_REF_L8=("8.0/5.0(L7)") | ByImpedance:75.0@_REF_L1=("6.5/4.0(L2)")|_REF_L6=("6.0/5.0(L5/L7)")|Type="DP"|_REF_L4=("7.0/6.0(L2/L5)" "5.5/4.0(L3/L5)")|_REF_L3=("7.0/6.0(L2/L5)")|imp="75.0"|_REF_L8=("6.5/4.0(L7)") | ByImpedance:80.0@_REF_L1=("6.5/5.0(L2)" "6.0/4.5(L2)")|_REF_L6=("5.0/5.0(L5/L7)")|Type="DP"|_REF_L4=("5.5/5.0(L2/L5)" "5.0/4.5(L3/L5)" "6.0/6.0(L2/L5)")|_REF_L3=("5.5/5.0(L2/L5)" "4.5/4.0(L2/L4)" "6.0/6.0(L2/L5)")|imp="80.0"|_REF_L8=("6.5/5.0(L7)" "6.0/4.5(L7)") | ByImpedance:83.0@_REF_L1=("5.5/4.5(L2)")|_REF_L6=("4.5/4.5(L5/L7)")|Type="DP"|_REF_L4=("4.5/4.0(L2/L5)" "4.5/4.5(L3/L5)")|_REF_L3=("4.5/4.0(L2/L5)" "4.5/4.5(L2/L4)")|imp="83.0"|_REF_L8=("5.5/4.5(L7)") | ByImpedance:85.0@_REF_L1=("5.5/5.0(L2)" "5.0/4.5(L2)" "6.0/6.0(L2)")|_REF_L6=("4.0/4.0(L5/L7)" "5.0/6.0(L5/L7)" "5.5/8.5(L5/L7)" "4.5/5.0(L5/L7)")|Type="DP"|_REF_L4=("4.0/4.0(L3/L5)" "5.5/7.0(L2/L5)" "5.0/6.0(L2/L5)" "5.0/5.5(L2/L5)" "4.5/4.5(L2/L5)")|_REF_L3=("4.0/4.0(L2/L5)" "5.5/7.0(L2/L5)" "5.0/6.0(L2/L5)" "5.0/5.5(L2/L5)" "4.5/4.5(L2/L5)")|imp="85.0"|_REF_L8=("5.5/5.0(L7)" "5.0/4.5(L7)" "6.0/6.0(L7)") | ByImpedance:88.0@_REF_L1=("4.5/4.0(L2)")|_REF_L6=("4.0/5.0(L5/L7)")|Type="DP"|_REF_L4=("4.0/4.5(L2/L5)" "3.5/4.0(L3/L5)")|_REF_L3=("4.0/4.5(L2/L5)")|imp="88.0"|_REF_L8=("4.5/4.0(L7)") | ByImpedance:90.0@_REF_L1=("4.0/4.0(L2)" "5.0/6.0(L2)")|_REF_L6=("4.0/5.5(L5/L7)")|Type="DP"|_REF_L4=("3.5/4.5(L3/L5)" "4.0/5.0(L2/L5)" "4.5/6.0(L2/L5)")|_REF_L3=("4.0/5.0(L2/L5)" "3.5/4.5(L2/L4)" "4.5/6.0(L2/L5)")|imp="90.0"|_REF_L8=("4.0/4.0(L7)" "5.0/6.0(L7)") | LayerIndex:nil | Source:8-1.3-3h.xls | artWorks:("_REF_L3" "_REF_L6" "_REF_L4" "_REF_L8" "_REF_L1") | gtImpOutlineUsed:BOARD GEOMETRY/PANEL_OUTLINE
User.34: Board Accuracy Check,Dec 26 11:28:21 2016,Passed | Dummy-Static-No Shape On Layer Check,Dec 26 11:28:22 2016,Passed | Split Plane Check,Jul 13 19:03:29 2016,Passed
User.39: AUD_AGND | GND
User.43: This gerber is just for your reference to find the DP impedance traces in layer L1. | DP IMPEDANCE TABLE: L1 | * - Denotes that this Impedance | is NOT used | IMP(Ohm) | *60.0 | *68.0 | *70.0 | *72.0 | *75.0 | *80.0 | 80.0 | *83.0 | *85.0 | 85.0 | *88.0 | 90.0 | *90.0 | *100.0 | 100.0 | *110.0 | WIDTH(mils) | 11.5/5.0 | 9.0/5.0 | 8.5/5.0 | 8.0/5.0 | 6.5/4.0 | 6.5/5.0 | 6.0/4.5 | 5.5/4.5 | 5.5/5.0 | 5.0/4.5 | 6.0/6.0 | 4.5/4.0 | 4.0/4.0 | 5.0/6.0 | 4.0/6.0 | 3.5/5.0 | 5.0/11.0 | 4.0/12.0 | 3.5/8.0 | TYPE | DP | Ref. Plane | L2
User.45: Note:Refer to DRILL layer for ELLIPSE drill direction | FIGURE | SIZE | 10.0 | 12.0 | 16.0 | 21.0 | 28.0 | 36.0 | 115.0 | 128.0 | 166.0 | 182.0 | 40.0 | 44.0 | 46.0 | 63.0 | 65.0 | 71.0 | 119.0 | 126.0 | 158.0 | 58.0x26.0 | 60.0x36.0 | 71.0x36.0 | 90.0x28.0 | 95.0x28.0 | DRILL CHART: TOP to BOTTOM | ALL UNITS ARE IN MILS | PLATED | NON-PLATED | QTY | 4411 | 16 | 745 | 19 | 18 | 8 | 5 | 6 | 4 | 1 | 2 | 7 | This gerber is just for your reference to find the SE impedance traces in layer L1. | This gerber is just for your reference to find the SE impedance traces in layer L6. | This gerber is just for your reference to find the SE impedance traces in layer L8. | This gerber is just for your reference to find the DP impedance traces in layer L6. | This gerber is just for your reference to find the SE impedance traces in layer L3. | This gerber is just for your reference to find the DP impedance traces in layer L8. | This gerber is just for your reference to find the DP impedance traces in layer L3. | This gerber is just for your reference to find the SE impedance traces in layer L4. | This gerber is just for your reference to find the DP impedance traces in layer L4. | DP IMPEDANCE TABLE: L3 | DP IMPEDANCE TABLE: L4 | DP IMPEDANCE TABLE: L6 | DP IMPEDANCE TABLE: L8 | SE IMPEDANCE TABLE: L1 | SE IMPEDANCE TABLE: L3 | SE IMPEDANCE TABLE: L4 | SE IMPEDANCE TABLE: L6 | SE IMPEDANCE TABLE: L8 | * - Denotes that this Impedance | is NOT used | Model | Taos | PCB_NO | 16852 | VER. | Layer | DRILL | L1 | L2VCC | L3 | L4 | TMASK | TPLACE | TSILK | TSMD | Designer | LYNN LIU | Date | 12/26/2016 | IMP(Ohm) | *27.4 | *60.0 | *33.0 | *68.0 | *35.0 | *70.0 | 35.0 | *37.5 | *72.0 | *39.0 | *75.0 | *40.0 | *80.0 | 80.0 | 45.0 | 83.0 | *45.0 | *48.0 | 85.0 | *83.0 | *85.0 | 50.0 | *52.0 | *55.0 | *50.0 | *88.0 | 90.0 | *100.0 | *90.0 | 100.0 | *110.0 | WIDTH(mils) | 11.0 | 9.0 | 8.5 | 7.0 | 6.0 | 5.5 | 5.0 | 4.5 | 13.5 | 15.0 | 8.0 | 7.5 | 4.0 | 3.5 | 11.5/5.0 | 9.0/5.0 | 8.5/5.0 | 8.0/5.0 | 6.5/4.0 | 6.5/5.0 | 6.0/4.5 | 5.5/4.5 | 5.5/5.0 | 5.0/4.5 | 6.0/6.0 | 4.5/4.0 | 4.0/4.0 | 5.0/6.0 | 4.0/6.0 | 3.5/5.0 | 5.0/11.0 | 4.0/12.0 | 3.5/8.0 | 9.0/4.0 | 9.5/4.0 | 7.5/4.0 | 7.0/4.0 | 7.0/5.0 | 7.0/6.0 | 6.0/4.0 | 4.5/4.5 | 5.5/4.0 | 5.5/7.0 | 5.0/5.5 | 4.0/4.5 | 4.0/5.0 | 3.5/4.5 | 4.5/6.0 | 4.0/9.0 | 3.5/7.0 | 3.5/4.0 | 3.5/7.5 | 10.5/5.0 | 7.5/5.0 | 6.0/5.0 | 5.0/5.0 | 5.5/8.5 | 4.5/5.0 | 4.0/5.5 | 4.0/10.0 | TYPE | SE | DP | Ref. Plane | L2 | L7 | L2/L5 | L3/L5 | L5/L7 | L2/L4 | BMASK | BPLACE | BSILK | BSMD | L5GND | L6 | L7GND | L8
